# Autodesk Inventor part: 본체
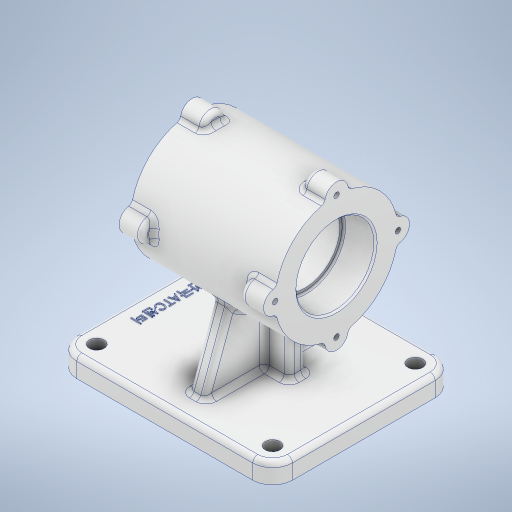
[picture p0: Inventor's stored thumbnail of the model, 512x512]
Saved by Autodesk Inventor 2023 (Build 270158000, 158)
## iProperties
Created: 2023-08
Part Number: 본체
Material: 알루미늄 6061
Document SubType Name: Modeling
Designer: asung
Density: 2.7 g/cm^3
Appearance: 알루미늄 - 평지
Author: asung
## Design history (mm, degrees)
sketch "스케치1"
  geometry: L1 (-53, 55)-(53, 55); L2 (65, 43)-(65, -43); L3 (53, -55)-(-53, -55); L4 (-65, -43)-(-65, 43); L5 (-65, 55)-(65, -55); L6 (65, 55)-(-65, -55); C1 r 4.5 at (53, -43); C2 r 4.5 at (53, 43); C3 r 4.5 at (-53, 43); C4 r 4.5 at (-53, -43); A1 r 12 centre (53, -43) between (53, -55) and (65, -43); A2 r 12 centre (53, 43) between (65, 43) and (53, 55); A3 r 12 centre (-53, 43) between (-53, 55) and (-65, 43); A4 r 12 centre (-53, -43) between (-65, -43) and (-53, -55); 1 further point
  constraints: 12 end point, 8 centre point, 8 point on circle, 8 point on line, 8 tangent, 4 coincident, 3 equal radius, 2 midpoint, 2 parallel, 1 horizontal, 1 perpendicular
  dimensions: "d0" = 130 distance of L5.end L6.end; "d1" = 110 distance of L6.start L5.end; "d2" = 12 radius of A1; "d3" = 9 diameter of C1; "d4" = 9 diameter of C2; "d5" = 9 diameter of C3; "d6" = 9 diameter of C4
extrude "돌출1" new body sketch "스케치1" distance "d7" = 12; taper "d8" = 0 deg
fillet "모깎기1" dims "d9" = 3
sketch "스케치2"
  geometry: L1 (-62, 12)-(62, 12) reference; L2 (65, 9)-(65, 0) reference; L3 (65, 0)-(-65, 0) reference; L4 (-65, 0)-(-65, 9) reference; L5 (-65, 0)-(5, 0); L6 (53, 0)-(-53, 0) reference; L7 (5, 0)-(5, 82); L8 (-38.5, 82)-(48.5, 82); L9 (48.5, 82)-(48.5, 119); L10 (48.5, 119)-(-38.5, 119); L11 (-38.5, 119)-(-38.5, 82); A1 r 3 centre (-62, 9) between (-62, 12) and (-65, 9) reference; A2 r 3 centre (62, 9) between (65, 9) and (62, 12) reference; 1 further point
  constraints: 12 end point, 2 perpendicular, 1 horizontal, 1 midpoint, 1 point on line, 1 vertical
  dimensions: "d15" = 70 distance of L3.end L5.end; "d16" = 82 distance of L7.end L5.end; "d17" = 87 distance of L8.start L8.end; "d18" = 37 distance of L8.end L9.end; "d19" = 87 distance of L9.end L10.end; "d20" = 37 distance of L10.end L8.start (derived)
revolve "회전1" sketch "스케치2" stored, may be unused: angle "d21" = 90 deg
sketch "스케치3"
  geometry: C1 r 37 at (0, 0) reference; 2 further points
  constraints: 1 coincident
hole "구멍1" sketch "스케치3" at (0, 0) diameter "d22" = 42; stored, may be unused: countersink angle "d26" = 90 deg, drill point angle "d28" = 118 deg; dims "d23" = 6, "d24" = 47, "d25" = 19, "d27" = 50
sketch "스케치4"
  geometry: C1 r 37 at (0, 0) reference; 2 further points
  constraints: 1 coincident
hole "구멍2" sketch "스케치4" at (0, 0) diameter "d29" = 42; stored, may be unused: countersink angle "d33" = 90 deg, drill point angle "d35" = 118 deg; dims "d30" = 6, "d31" = 47, "d32" = 19, "d34" = 50
chamfer "모따기1" distance "d36" = 1; stored, may be unused: second distance "d37" = 2, angle "d38" = 45 deg
fillet "모깎기2" dims "d39" = 1
sketch "스케치5"
  geometry: C1 r 37 at (0, 0) reference; C2 r 7 at (0, 37); 4 further points
  constraints: 1 centre point, 1 vertical alignment, 1 other
  dimensions: "d40" = 14 diameter of C2
extrude "돌출2" join sketch "스케치5" distance "d41" = 14; taper "d42" = 0 deg
fillet "모깎기3" dims "d43" = 3
fillet "모깎기4" dims "d44" = 3
node "작업 평면1"
sketch "스케치6"
  geometry: A1 r 7 centre (0, 0) between (6.889, 1.239) and (-6.889, 1.239) reference; 2 further points
  constraints: 1 coincident
hole "구멍3" sketch "스케치6" at (0, 0) diameter "d48" = 3.242; stored, may be unused: countersink angle "d52" = 90 deg, drill point angle "d54" = 118 deg; dims "d49" = 8, "d50" = 19.05, "d51" = 4.775, "d53" = 10
sketch "스케치7"
  geometry: L1 (53, 55)-(-53, 55) reference; L2 (65, -43)-(65, 43) reference; L3 (-53, -55)-(53, -55) reference; L4 (-65, 43)-(-65, -43) reference; C1 r 4.5 at (53, 43) reference; C2 r 4.5 at (53, -43) reference; C3 r 4.5 at (-53, -43) reference; C4 r 4.5 at (-53, 43) reference; A1 r 12 centre (53, 43) between (65, 43) and (53, 55) reference; A2 r 12 centre (53, -43) between (53, -55) and (65, -43) reference; A3 r 12 centre (-53, -43) between (-65, -43) and (-53, -55) reference; A4 r 12 centre (-53, 43) between (-53, 55) and (-65, 43) reference
  node "투영된 루프1"
sketch "스케치8"
  geometry: L1 (-52, -107)-(52, -107) reference; L2 (55, -110)-(55, -119) reference; L3 (55, -119)-(-55, -119) reference; L4 (-55, -119)-(-55, -110) reference; L5 (55, -119)-(55, -110) reference; L6 (38.5, -107)-(47.5, -107) reference; L7 (41, -107)-(22.198, -55.343); L8 (-47.5, -107)-(-38.5, -107) reference; L9 (-41, -107)-(-25.336, -63.964); L10 (-25.336, -63.964)-(-23.165, -58); L11 (-23.165, -58)-(-10.082, -63.964); L12 (-10.082, -63.964)-(14.522, -60.982); L13 (14.522, -60.982)-(22.198, -55.343); C1 r 21 at (0, -37) reference; A1 r 3 centre (-52, -110) between (-52, -107) and (-55, -110) reference; A2 r 3 centre (52, -110) between (55, -110) and (52, -107) reference; 3 further points
  constraints: 12 end point, 2 point on line, 2 other
  dimensions: "d65" = 110 deg angle of L1 L9
  node "절단 모서리 투영2"
extrude "돌출4" join sketch "스케치8" stored distance "d80" = 10; taper "d81" = 0 deg
fillet "모깎기7" dims "d82" = 3
fillet "모깎기8" dims "d83" = 3
node "작업 평면2"
sketch "스케치9"
  geometry: L1 (28, 12)-(68, 12); L2 (50, 12)-(46, 12) reference; L3 (28, 12)-(28, 50.054); L4 (28, 50.054)-(68, 50.054); L5 (68, 50.054)-(68, 12); 2 further points
  constraints: 8 end point, 2 midpoint, 1 horizontal, 1 perpendicular, 1 vertical
  dimensions: "d84" = 40 distance of L1.start L1.end; "d85" = 40 distance of L3.end L4.end
extrude "돌출5" join sketch "스케치9" stored distance "d86" = 10; taper "d87" = 0 deg
fillet "모깎기9" dims "d88" = 3
fillet "모깎기10" dims "d89" = 3
sketch "스케치10"
  geometry: L1 (-65, 43)-(-65, -43) reference; L2 (7, 43.101)-(3, 43.101) reference; 4 further points
  constraints: 2 midpoint, 1 other
  dimensions: "d92" = 0 vertical distance of point (-65, 0) point (-53, 0); "d96" = 58 horizontal distance of point (-53, 0) point (5, 43.101)
feature "엠보싱1" sketch "스케치10" dims "d0" = 130, "d1" = 110, "d2" = 12, "d3" = 9, "d4" = 9, "d5" = 9, "d6" = 9, "d9" = 3, "d93" = 0.5, "d94" = 0
node "작업 평면3"
sketch "스케치11"
  geometry: 1 further point
fillet "모깎기11" dims "d95" = 3
node "솔리드1"
pattern_circular "원형 패턴1" dims angle "d46" = 360 deg
mirror "미러1"
pattern_circular "원형 패턴2" dims angle "d56" = 360 deg
mirror "미러2"
node "절단 모서리 투영1"
feature "A9D066F2-1C7D-4E18-AEED-F7BC21143FA4" dims "d22" = 42, "d23" = 6, "d24" = 47, "d25" = 19, "d26" = 90 deg, "d27" = 50, "d28" = 118 deg
